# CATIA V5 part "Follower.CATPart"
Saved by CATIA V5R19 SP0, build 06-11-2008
Part number: Follower
Bounding box of the stored display mesh (mm): x -9.942 to 9.942, y -9.942 to 9.942, z 0 to 100
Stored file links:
  D:\Shriniwas\v5_r19\c16_CAT_v5r19\c16_Part\Cam_Follower_msm_trial\Follower.CATPart
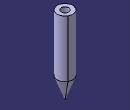
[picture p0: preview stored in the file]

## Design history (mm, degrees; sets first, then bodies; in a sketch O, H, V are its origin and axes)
Body1 (main body)
  Sketch1 on yz-plane, origin (0, 0, 0), H (0, 1, 0), V (0, 0, 1)
    line L1 (0, 0) -> (10, 27.4748)
    point P1 (10, 27.4748)
    line L2 (10, 27.4748) -> (10, 100)
    point P2 (10, 27.4748)
    point P3 (10, 100)
    point P4 (0, 100)
    point P5 (10, 91.3901)
    line L3 (0, 0) -> (0, 100)
    reference intersected line E1 through (0, 0) direction (-1, 0) from xy-plane
    reference intersected line E3 through (0, 0) direction (0, 1) from zx-plane
    line L4 (0, 100) -> (10, 100)
    point P6 (10, 100)
    angle L1 L3 = 20
    distance O P4 = 100
    length L4 = 10
    coincidence: P2 L1, P4 V, P5 L2, P2 P1, E3 P4, P1 L2, P6 L2, P6 P3
    vertical: L2 V, L3 V, E3 V
    horizontal: E1 H, L4 H
    perpendicularity: E1 L2
  Shaft1: profile Sketch1, axis Sketch1.L3, angle 360
  Sketch2 on face of Shaft1 from Sketch1.L4, origin (0, 0, 100), H (1, 0, 0), V (0, 1, 0)
    point P1 (0, 0)
  Hole1: placed by Sketch2, at (0, 0, 100) direction (0, 0, -1), diameter 10, depth 55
